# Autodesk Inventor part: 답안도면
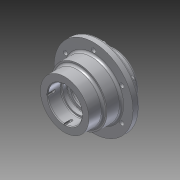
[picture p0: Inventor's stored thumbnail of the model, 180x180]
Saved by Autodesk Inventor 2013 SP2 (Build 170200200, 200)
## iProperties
Created: 2024-04
Part Number: 답안도면
Material: 알루미늄 6061
Document SubType Name: Modeling
Designer: a
Density: 2.71 g/cm^3
Mass: 578.599 g
Surface Area: 456.347 cm^2
Volume: 213.505 cm^3
Author: a
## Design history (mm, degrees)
sketch "스케치1"
  geometry: C1 r 54.5 at (0, 0); 1 further point
  constraints: 1 centre point, 1 coincident
  dimensions: "d0" = 109 diameter of C1
extrude "돌출1" new body sketch "스케치1" distance "d2" = 10; taper "d3" = 0 deg
sketch "스케치2"
  geometry: C1 r 54.5 at (0, 0) reference; C2 r 38.5 at (0, 0)
  constraints: 1 centre point, 1 coincident
  dimensions: "d4" = 77 diameter of C2
extrude "돌출2" join sketch "스케치2" distance "d6" = 20; taper "d7" = 0 deg
sketch "스케치3"
  geometry: C1 r 38.5 at (0, 0) reference; C2 r 33.5 at (0, 0)
  constraints: 1 centre point, 1 coincident
  dimensions: "d8" = 67 diameter of C2
extrude "돌출3" join sketch "스케치3" distance "d11" = 20; taper "d12" = 0 deg
fillet "모깎기1" dims "d13" = 3
sketch "스케치4"
  geometry: C1 r 33.5 at (0, 0) reference; C2 r 23.5 at (0, 0)
  constraints: 1 centre point, 1 coincident
  dimensions: "d14" = 47 diameter of C2
extrude "돌출4" cut sketch "스케치4" distance "d16" = 18; taper "d17" = 0 deg
sketch "스케치5"
  geometry: C1 r 23.5 at (0, 0) reference; C2 r 20.5 at (0, 0)
  constraints: 1 centre point, 1 coincident
  dimensions: "d18" = 41 diameter of C2
extrude "돌출5" cut sketch "스케치5" distance "d21" = 6; taper "d22" = 0 deg
sketch "스케치6"
  geometry: C1 r 54.5 at (0, 0) reference; C2 r 23.5 at (0, 0)
  constraints: 1 centre point, 1 coincident
  dimensions: "d23" = 47 diameter of C2
extrude "돌출6" cut sketch "스케치6" distance "d25" = 18; taper "d26" = 0 deg
sketch "스케치7"
  geometry: C1 r 23.5 at (0, 0) reference; C2 r 20.5 at (0, 0)
  constraints: 1 centre point, 1 coincident
  dimensions: "d27" = 41 diameter of C2
extrude "돌출7" cut sketch "스케치7" distance "d30" = 6; taper "d31" = 0 deg
sketch "스케치8"
  geometry: C1 r 20.5 at (0, 0) reference; C2 r 16 at (0, 0)
  constraints: 1 centre point, 1 coincident
  dimensions: "d32" = 32 diameter of C2
extrude "돌출8" cut sketch "스케치8" stored distance "d34" = 6; taper "d35" = 0 deg
sketch "스케치9"
  geometry: C1 r 23.5 at (0, 0) reference; C2 r 54.5 at (0, 0) reference; C3 r 25.5 at (0, 0)
  constraints: 1 centre point, 1 coincident
  dimensions: "d36" = 51 diameter of C3
extrude "돌출9" join sketch "스케치9" distance "d38" = 6; taper "d39" = 0 deg
sketch "스케치10"
  geometry: C1 r 54.5 at (0, 0) reference; C2 r 33.5 at (0, 0); 1 further point
  constraints: 1 centre point, 1 coincident, 1 vertical alignment, 1 other
  dimensions: "d40" = 67 diameter of C2; "d45" = 6 distance of C1.centre point (0, 6)
extrude "돌출10" join sketch "스케치10" distance "d42" = 20; taper "d43" = 0 deg
fillet "모깎기2" dims "d44" = 3
fillet "모깎기3" dims "d106" = 3
fillet "모깎기4" dims "d107" = 3
sketch "스케치14"
  geometry: C1 r 36.5 at (0, 0) reference; C2 r 3.5 at (0, 45); C3 r 3.5 at (-38.971, 22.5); C4 r 3.5 at (-38.971, -22.5); C5 r 3.5 at (0, -45); C6 r 3.5 at (38.971, -22.5); C7 r 3.5 at (38.971, 22.5)
  constraints: 6 centre point, 1 vertical alignment, 13 other
  dimensions: "d108" = 45 distance of C1.centre C2.centre; "d109" = 7 diameter of C2; "d112" = 360 deg dimension on C1.centre C2.centre (derived)
extrude "돌출13" join sketch "스케치14" distance "d114" = 5; taper "d115" = 0 deg
sketch "스케치16"
  geometry: C1 r 30.5 at (0, 0) reference; C2 r 23.5 at (0, 0)
  constraints: 1 centre point, 1 coincident
  dimensions: "d131" = 47 diameter of C2
extrude "돌출14" cut sketch "스케치16" distance "d133" = 18; taper "d134" = 0 deg
sketch "스케치17"
  geometry: C1 r 23.5 at (0, 0) reference; C2 r 16 at (0, 0)
  constraints: 1 centre point, 1 coincident
  dimensions: "d135" = 32 diameter of C2
extrude "돌출15" cut sketch "스케치17" distance "d137" = 6; taper "d138" = 0 deg
fillet "모깎기5" dims "d146" = 3
chamfer "모따기1" distance "d147" = 1; stored, may be unused: second distance "d148" = 2, angle "d149" = 45 deg
sketch "스케치20" dims "d151" = 47
  geometry: C1 r 54.5 at (0, 0) reference; C2 r 41.5 at (0, 0) reference; 8 further points
  constraints: 3 coincident, 3 vertical alignment, 2 horizontal alignment, 19 other
  dimensions: "d155" = 360 deg dimension on point (0, 0) point (0, 23.5) (derived)
hole "구멍8" sketch "스케치20" at (0, 23.5), (-23.5, 0), (0, -23.5), (23.5, 0) diameter "d157" = 3.242; stored, may be unused: countersink angle "d161" = 90 deg, drill point angle "d163" = 118 deg; dims "d158" = 8, "d159" = 4, "d160" = 2, "d162" = 10
fillet "모깎기6" dims "d164" = 1
fillet "모깎기7" dims "d165" = 1
chamfer "모따기2" distance "d166" = 0.6; stored, may be unused: second distance "d167" = 2, angle "d168" = 45 deg
sketch "스케치21" dims "d169" = 47
  geometry: C1 r 33.5 at (0, 0) reference; C2 r 24.5 at (0, 0) reference; 5 further points
  constraints: 2 vertical alignment, 1 coincident, 7 other
  dimensions: "d173" = 360 deg dimension on point (0, 0) point (0, 23.5) (derived)
hole "구멍9" sketch "스케치21" at (0, 23.5), (-23.5, 0), (0, -23.5), (23.5, 0) diameter "d175" = 3.242; stored, may be unused: countersink angle "d179" = 90 deg, drill point angle "d181" = 118 deg; dims "d176" = 8, "d177" = 4, "d178" = 2, "d180" = 10
hole "구멍10" diameter "d184" = 6; stored, may be unused: countersink angle "d188" = 90 deg, drill point angle "d190" = 0 deg; dims "d182" = 10, "d183" = 10, "d185" = 8, "d186" = 4, "d187" = 2, "d189" = 10
hole "구멍11" diameter "d193" = 6; stored, may be unused: countersink angle "d197" = 90 deg, drill point angle "d199" = 0 deg; dims "d191" = 10, "d192" = 10, "d194" = 8, "d195" = 4, "d196" = 2, "d198" = 10
hole "구멍12" diameter "d202" = 6; stored, may be unused: countersink angle "d206" = 90 deg, drill point angle "d208" = 0 deg; dims "d200" = 10, "d201" = 10, "d203" = 8, "d204" = 4, "d205" = 2, "d207" = 10
hole "구멍13" diameter "d211" = 6; stored, may be unused: countersink angle "d215" = 90 deg, drill point angle "d217" = 0 deg; dims "d209" = 10, "d210" = 10, "d212" = 8, "d213" = 4, "d214" = 2, "d216" = 10
hole "구멍14" diameter "d220" = 6; stored, may be unused: countersink angle "d224" = 90 deg, drill point angle "d226" = 0 deg; dims "d218" = 10, "d219" = 10, "d221" = 8, "d222" = 4, "d223" = 2, "d225" = 10
hole "구멍15" diameter "d229" = 6; stored, may be unused: countersink angle "d233" = 90 deg, drill point angle "d235" = 0 deg; dims "d227" = 10, "d228" = 10, "d230" = 8, "d231" = 4, "d232" = 2, "d234" = 10
node "솔리드1"
